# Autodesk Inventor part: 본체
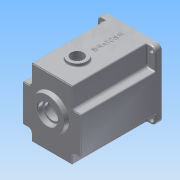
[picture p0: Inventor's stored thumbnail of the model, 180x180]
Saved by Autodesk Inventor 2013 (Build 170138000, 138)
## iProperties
Created: 2016-02
Part Number: 본체
Material: 알루미늄 6061
Document SubType Name: Modeling
Designer: mduedu
Density: 1 g/cm^3
Author: mduedu
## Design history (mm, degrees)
sketch "스케치1"
  geometry: L1 (-47, -47)-(47, -47); L2 (47, -47)-(47, 63); L3 (47, 63)-(-47, 63); L4 (-47, 63)-(-47, -47); 2 further points
  constraints: 8 end point, 2 parallel, 1 horizontal, 1 midpoint, 1 perpendicular, 1 vertical alignment
  dimensions: "d0" = 94 distance of L2.end L3.end; "d155" = 110 distance of L1.end L2.end; "d156" = 47 distance from line of L1 point (0, 0)
extrude "돌출1" new body sketch "스케치1" distance "d2" = 130; taper "d3" = 0 deg
sketch "스케치3"
  geometry: C1 r 40 at (0, 0); 1 further point
  constraints: 1 centre point, 1 coincident
  dimensions: "d9" = 80 diameter of C1
extrude "돌출3" cut sketch "스케치3" distance "d11" = 121; taper "d12" = 0 deg
sketch "스케치4"
  geometry: C1 r 21 at (0, 11); 1 further point
  constraints: 1 centre point, 1 vertical alignment
  dimensions: "d13" = 21 radius of C1; "d15" = 11 distance of point (0, 0) C1.centre
extrude "돌출4" join sketch "스케치4" distance "d16" = 7; taper "d17" = 0 deg
sketch "스케치5"
  geometry: C1 r 15 at (0, -20); 1 further point
  constraints: 1 centre point, 1 vertical alignment
  dimensions: "d18" = 15 radius of C1; "d20" = 20 distance of point (0, 0) C1.centre
extrude "돌출5" join sketch "스케치5" distance "d21" = 7; taper "d22" = 0 deg
sketch "스케치6"
  geometry: C1 r 28 at (0, 11); A1 r 21 centre (0, 11) between (8.978, -7.984) and (-8.978, -7.984) reference; 1 further point
  constraints: 1 centre point, 1 coincident
  dimensions: "d23" = 56 diameter of C1
extrude "돌출6" join sketch "스케치6" distance "d25" = 7; taper "d26" = -10 deg
hole "구멍1" diameter "d29" = 35; stored, may be unused: countersink angle "d33" = 90 deg, drill point angle "d35" = 0 deg; dims "d27" = 10, "d28" = 10, "d30" = 6, "d31" = 4, "d32" = 2, "d34" = 10
hole "구멍2" diameter "d38" = 22; stored, may be unused: countersink angle "d42" = 90 deg, drill point angle "d44" = 0 deg; dims "d36" = 10, "d37" = 10, "d39" = 6, "d40" = 4, "d41" = 2, "d43" = 7
hole "구멍3" diameter "d47" = 19; stored, may be unused: countersink angle "d51" = 90 deg, drill point angle "d53" = 0 deg; dims "d45" = 10, "d46" = 10, "d48" = 6, "d49" = 4, "d50" = 2, "d52" = 1
hole "구멍4" diameter "d56" = 32; stored, may be unused: countersink angle "d60" = 90 deg, drill point angle "d62" = 0 deg; dims "d54" = 10, "d55" = 10, "d57" = 6, "d58" = 4, "d59" = 2, "d61" = 8
hole "구멍5" diameter "d65" = 25; stored, may be unused: countersink angle "d69" = 90 deg, drill point angle "d71" = 0 deg; dims "d63" = 10, "d64" = 10, "d66" = 6, "d67" = 4, "d68" = 2, "d70" = 8
fillet "모깎기2" dims "d73" = 0.3
fillet "모깎기3" dims "d74" = 2
chamfer "모따기1" distance "d75" = 1; stored, may be unused: second distance "d76" = 2, angle "d77" = 45 deg
fillet "모깎기4" dims "d78" = 3
sketch "스케치16"
  geometry: L1 (-23, 32.726)-(23, 32.726); L2 (23, 32.726)-(23, 53); L3 (23, 53)-(-23, 53); L4 (-23, 53)-(-23, 32.726); L5 (-47, 63)-(47, 63) reference; 3 further points
  constraints: 8 end point, 2 parallel, 1 horizontal, 1 midpoint, 1 perpendicular, 1 vertical alignment, 2 other
  dimensions: "d160" = 46 distance of L2.end L3.end; "d163" = 10 distance between parallel lines of L3 L5
extrude "돌출15" cut sketch "스케치16" stored distance "d164" = 10; taper "d165" = 0 deg
fillet "모깎기5" dims "d79" = 2
fillet "모깎기15" dims "d166" = 5
sketch "스케치7"
  geometry: L1 (-23, 48)-(-23, 35.228) reference; L2 (23, 35.228)-(23, 48) reference; L3 (18, 53)-(-18, 53) reference; L4 (47, 63)-(47, -47) reference; L5 (47, -47)-(-47, -47) reference; L6 (-47, -47)-(-47, 63) reference; L7 (-47, 63)-(47, 63) reference; L8 (-26, 48)-(-26, 35.228); L9 (26, 35.228)-(26, 48); L10 (18, 56)-(-18, 56); C1 r 43 at (0, 0); A1 r 5 centre (-18, 48) between (-18, 53) and (-23, 48) reference; A2 r 5 centre (-28, 35.228) between (-24.889, 31.314) and (-23, 35.228) reference; A3 r 40 centre (0, 0) between (-24.889, 31.314) and (24.889, 31.314) reference; A4 r 5 centre (28, 35.228) between (23, 35.228) and (24.889, 31.314) reference; A5 r 5 centre (18, 48) between (23, 48) and (18, 53) reference; A6 r 8 centre (-18, 48) between (-18, 56) and (-26, 48); A7 r 2 centre (-28, 35.228) between (-26.756, 33.662) and (-26, 35.228); A8 r 43 centre (0, 0) between (-26.756, 33.662) and (26.756, 33.662); A9 r 2 centre (28, 35.228) between (26, 35.228) and (26.756, 33.662); A10 r 8 centre (18, 48) between (26, 48) and (18, 56); 1 further point
  constraints: 10 point on circle, 6 centre point, 6 end point, 1 coincident, 7 other
  dimensions: "d80" = 86 diameter of C1; "d167" = 3 distance between parallel lines of L3 L10
extrude "돌출7" cut sketch "스케치7" distance "d83" = 9; taper "d84" = 0 deg
sketch "스케치8" dims "d168" = 36
  geometry: L1 (-36, 4)-(-39.799, 4); L2 (-36, -4)-(-39.799, -4); A1 r 4 centre (-36, 0) between (-36, 4) and (-36, -4); A2 r 40 centre (0, 0) between (-24.889, 31.314) and (24.889, 31.314) reference; A3 r 40 centre (0, 0) between (-39.799, 4) and (-39.799, -4); 2 further points
  constraints: 5 point on circle, 4 end point, 2 centre point, 2 coincident, 2 horizontal alignment, 2 tangent, 1 horizontal, 1 parallel, 2 other
  dimensions: "d169" = 4 radius of A1
extrude "돌출9" join sketch "스케치8" stored distance "d89" = 9; taper "d90" = 0 deg
fillet "모깎기6" dims "d91" = 3.5
sketch "스케치9"
  geometry: L1 (47, 63)-(-47, 63) reference; L2 (47, -47)-(47, 63) reference; L3 (47, 63)-(33, 63); L4 (33, 63)-(33, 30); L5 (33, 30)-(47, 30); L6 (47, 30)-(47, 63); 2 further points
  constraints: 8 end point, 2 parallel, 1 horizontal, 1 perpendicular
  dimensions: "d95" = 33 distance from line of L4 point (0, 0); "d96" = 30 distance from line of L5 point (0, 0)
extrude "돌출10" cut sketch "스케치9" distance "d97" = 120; taper "d98" = 0 deg
sketch "스케치11"
  geometry: L1 (-40, -40)-(40, -40); L2 (40, -40)-(40, 56); L3 (40, 56)-(-40, 56); L4 (-40, 56)-(-40, -40); L5 (-47, -47)-(47, -47) reference; L6 (47, 63)-(-47, 63) reference; L7 (-47, 63)-(-47, -47) reference; C1 r 3.5 at (-40, 56); C2 r 3.5 at (40, 56); C3 r 3.5 at (40, -40); C4 r 3.5 at (-40, -40); 1 further point
  constraints: 8 end point, 4 centre point, 4 coincident, 3 equal radius, 2 parallel, 1 horizontal, 1 perpendicular
  dimensions: "d109" = 80 distance of L2.end L3.end; "d112" = 7 diameter of C1; "d157" = 7 distance from line of L1.start L5; "d158" = 7 distance between parallel lines of L6 L3; "d159" = 7 distance from line of L7 L3.end
extrude "돌출12" cut sketch "스케치11" stored distance "d113" = 63; taper "d114" = 0 deg
fillet "모깎기7" dims "d115" = 8
fillet "모깎기8" dims "d116" = 5
fillet "모깎기11" dims "d119" = 2
fillet "모깎기12" dims "d120" = 2
fillet "모깎기13" dims "d121" = 2
sketch "스케치12"
  geometry: 3 further points
  constraints: 2 horizontal alignment
hole "구멍6" sketch "스케치12" at (36, 0), (-36, 0) diameter "d122" = 3.242; stored, may be unused: countersink angle "d126" = 90 deg, drill point angle "d128" = 120 deg; dims "d123" = 7, "d124" = 4, "d125" = 2, "d127" = 9
sketch "스케치13"
  geometry: L1 (-33, 35)-(-33, 61) reference; L2 (-31, 63)-(31, 63) reference; L3 (33, 61)-(33, 35) reference; L4 (33, -35)-(33, -45) reference; L5 (31, -47)-(-31, -47) reference; L6 (-33, -45)-(-33, -35) reference; L7 (38, 30)-(45, 30) reference; L8 (47, 28)-(47, -28) reference; L9 (45, -30)-(38, -30) reference; L10 (-38, -30)-(-45, -30) reference; L11 (-47, -28)-(-47, 28) reference; L12 (-45, 30)-(-38, 30) reference; L13 (31, 62)-(-31, 62); L14 (-32, 61)-(-32, 35); L15 (-38, 29)-(-45, 29); L16 (-46, 28)-(-46, -28); L17 (-45, -29)-(-38, -29); L18 (-32, -35)-(-32, -45); L19 (-31, -46)-(31, -46); L20 (32, -45)-(32, -35); L21 (38, -29)-(45, -29); L22 (46, -28)-(46, 28); L23 (45, 29)-(38, 29); L24 (32, 35)-(32, 61); L25 (38, 30)-(45, 30) reference; L26 (47, 28)-(47, -28) reference; L27 (45, -30)-(38, -30) reference; L28 (33, -35)-(33, -45) reference; L29 (31, -47)-(-31, -47) reference; L30 (-33, -45)-(-33, -35) reference; L31 (-38, -30)-(-45, -30) reference; L32 (-47, -28)-(-47, 28) reference; L33 (-45, 30)-(-38, 30) reference; L34 (-33, 35)-(-33, 61) reference; L35 (33, 61)-(33, 35) reference; L36 (-31, 63)-(31, 63) reference; C1 r 16 at (0, 11) reference; C2 r 28 at (0, 11) reference; C3 r 16 at (0, 11) reference; C4 r 28 at (0, 11) reference; A1 r 5 centre (-38, 35) between (-38, 30) and (-33, 35) reference; A2 r 2 centre (-31, 61) between (-31, 63) and (-33, 61) reference; A3 r 2 centre (31, 61) between (33, 61) and (31, 63) reference; A4 r 5 centre (38, 35) between (33, 35) and (38, 30) reference; A5 r 5 centre (38, -35) between (38, -30) and (33, -35) reference; A6 r 2 centre (31, -45) between (31, -47) and (33, -45) reference; A7 r 2 centre (-31, -45) between (-33, -45) and (-31, -47) reference; A8 r 5 centre (-38, -35) between (-33, -35) and (-38, -30) reference; A9 r 2 centre (45, 28) between (47, 28) and (45, 30) reference; A10 r 2 centre (45, -28) between (45, -30) and (47, -28) reference; A11 r 2 centre (-45, -28) between (-47, -28) and (-45, -30) reference; A12 r 2 centre (-45, 28) between (-45, 30) and (-47, 28) reference; A13 r 1 centre (-31, 61) between (-31, 62) and (-32, 61); A14 r 6 centre (-38, 35) between (-38, 29) and (-32, 35); A15 r 1 centre (-45, 28) between (-45, 29) and (-46, 28); A16 r 1 centre (-45, -28) between (-46, -28) and (-45, -29); A17 r 6 centre (-38, -35) between (-32, -35) and (-38, -29); A18 r 1 centre (-31, -45) between (-32, -45) and (-31, -46); A19 r 1 centre (31, -45) between (31, -46) and (32, -45); A20 r 6 centre (38, -35) between (38, -29) and (32, -35); A21 r 1 centre (45, -28) between (45, -29) and (46, -28); A22 r 1 centre (45, 28) between (46, 28) and (45, 29); A23 r 6 centre (38, 35) between (32, 35) and (38, 29); A24 r 1 centre (31, 61) between (32, 61) and (31, 62); A25 r 5 centre (38, 35) between (33, 35) and (38, 30) reference; A26 r 2 centre (45, 28) between (47, 28) and (45, 30) reference; A27 r 2 centre (45, -28) between (45, -30) and (47, -28) reference; A28 r 5 centre (38, -35) between (38, -30) and (33, -35) reference; A29 r 2 centre (31, -45) between (31, -47) and (33, -45) reference; A30 r 2 centre (-31, -45) between (-33, -45) and (-31, -47) reference; A31 r 5 centre (-38, -35) between (-33, -35) and (-38, -30) reference; A32 r 2 centre (-45, -28) between (-47, -28) and (-45, -30) reference; A33 r 2 centre (-45, 28) between (-45, 30) and (-47, 28) reference; A34 r 5 centre (-38, 35) between (-38, 30) and (-33, 35) reference; A35 r 2 centre (-31, 61) between (-31, 63) and (-33, 61) reference; A36 r 2 centre (31, 61) between (33, 61) and (31, 63) reference
  constraints: 24 end point, 24 point on circle, 12 centre point, 23 other
  dimensions: "d154" = 1 distance between parallel lines of L13 L2
extrude "돌출13" cut sketch "스케치13" distance "d130" = 1; taper "d131" = 0 deg
fillet "모깎기14" dims "d147" = 0.3
sketch "스케치15"
  geometry: L1 (78, 0)-(0, 0) reference; 3 further points
  constraints: 1 midpoint, 1 vertical alignment, 1 other
  dimensions: "d148" = 40 distance of point (39, -40) point (39, 0)
feature "엠보싱1" sketch "스케치15" dims "d22" = 0, "d149" = 0.5, "d150" = 0
chamfer "모따기4" distance "d151" = 1; stored, may be unused: second distance "d152" = 2, angle "d153" = 45 deg
sketch "스케치17"
  geometry: L1 (39.004, -17.213)-(39.004, -18.809) reference; L2 (39.004, -18.809)-(38.548, -18.809) reference; L3 (38.548, -18.809)-(38.548, -17.213) reference; L4 (38.548, -17.213)-(35.455, -17.213) reference; L5 (35.455, -17.213)-(35.455, -16.822) reference; L6 (35.772, -16.659)-(42.578, -16.659) reference; L7 (42.578, -16.659)-(42.578, -17.213) reference; L8 (42.578, -17.213)-(39.004, -17.213) reference; L9 (38.223, -56.73)-(38.695, -56.73) reference; L10 (38.695, -56.73)-(38.695, -58.073) reference; L11 (38.695, -58.073)-(40.787, -58.073) reference; L12 (40.787, -58.073)-(40.787, -58.643) reference; L13 (40.787, -58.643)-(35.398, -58.643) reference; L14 (35.398, -58.643)-(35.398, -58.277) reference; L15 (35.715, -58.073)-(38.223, -58.073) reference; L16 (38.223, -58.073)-(38.223, -56.73) reference; L17 (41.927, -57.813)-(42.383, -57.813) reference; L18 (42.383, -57.813)-(42.383, -63.031) reference; L19 (42.383, -63.031)-(40.429, -63.031) reference; L20 (40.429, -63.031)-(40.429, -62.608) reference; L21 (40.689, -62.478)-(41.927, -62.478) reference; L22 (41.927, -62.478)-(41.927, -57.813) reference; L23 (36.09, -60.849)-(36.09, -62.624) reference; L24 (36.09, -62.624)-(35.666, -62.624) reference; L25 (35.666, -62.624)-(35.666, -60.849) reference; L26 (35.666, -60.849)-(36.09, -60.849) reference; L27 (37.058, -64.057)-(36.635, -64.057) reference; L28 (36.635, -64.057)-(36.635, -59.539) reference; L29 (36.635, -59.539)-(37.058, -59.539) reference; L30 (37.058, -59.539)-(37.058, -64.057) reference; L31 (42.138, -43.501)-(40.307, -44.168) reference; L32 (40.307, -44.168)-(40.307, -46.871) reference; L33 (40.307, -46.871)-(42.138, -47.555) reference; L34 (42.138, -47.555)-(42.138, -48.133) reference; L35 (42.138, -48.133)-(36.138, -45.853) reference; L36 (36.138, -45.853)-(36.138, -45.202) reference; L37 (36.138, -45.202)-(42.138, -42.923) reference; L38 (42.138, -42.923)-(42.138, -43.501) reference; L39 (36.725, -45.536)-(39.81, -46.684) reference; L40 (39.81, -46.684)-(39.81, -44.364) reference; L41 (39.81, -44.364)-(36.725, -45.536) reference; L42 (40.022, -52.114)-(40.022, -49.94) reference; L43 (40.022, -49.94)-(42.57, -49.94) reference; L44 (42.57, -49.94)-(42.57, -50.494) reference; L45 (42.57, -50.494)-(40.469, -50.494) reference; L46 (40.469, -50.494)-(40.469, -55.094) reference; L47 (40.469, -55.094)-(40.022, -55.094) reference; L48 (40.022, -55.094)-(40.022, -52.659) reference; L49 (40.022, -52.659)-(38.556, -52.659) reference; L50 (38.556, -52.659)-(38.556, -55.973) reference; L51 (38.556, -55.973)-(38.109, -55.973) reference; L52 (38.109, -55.973)-(38.109, -50.73) reference; L53 (36.106, -50.388)-(36.106, -54.955) reference; L54 (36.106, -54.955)-(35.65, -54.955) reference; L55 (35.65, -54.955)-(35.65, -49.81) reference; L56 (38.109, -50.136)-(38.109, -48.768) reference; L57 (38.109, -48.768)-(38.556, -48.768) reference; L58 (38.556, -48.768)-(38.556, -52.114) reference; L59 (38.556, -52.114)-(40.022, -52.114) reference; L60 (36.138, -38.168)-(36.635, -38.168) reference; L61 (36.635, -38.168)-(36.635, -40.041) reference; L62 (36.635, -40.041)-(42.138, -40.041) reference; L63 (42.138, -40.041)-(42.138, -40.586) reference; L64 (42.138, -40.586)-(36.635, -40.586) reference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; C1 r 10 at (39, -89); A1 r 4 centre (4, -12) between (8, -12) and (4, -8) reference; A2 r 4 centre (74, -12) between (74, -8) and (70, -12) reference; 61 further points
  constraints: 2 end point, 1 centre point, 1 midpoint, 1 point on line, 76 other
  dimensions: "d170" = 20 diameter of C1; "d171" = 41 distance from line of C1.centre L110
extrude "돌출16" cut sketch "스케치17" stored distance "d172" = 10; taper "d173" = 0 deg
sketch "스케치18"
  geometry: C1 r 10 at (39, -89) reference; C2 r 15 at (39, -89); 1 further point
  constraints: 1 centre point, 1 coincident
  dimensions: "d174" = 30 diameter of C2
extrude "돌출17" join sketch "스케치18" distance "d175" = 5; taper "d176" = 0 deg
fillet "모깎기16" dims "d177" = 2
sketch "스케치19"
  geometry: C1 r 10 at (18, 80) reference; C2 r 15 at (18, 80); 1 further point
  constraints: 1 centre point, 1 coincident
  dimensions: "d178" = 30 diameter of C2
extrude "돌출18" cut sketch "스케치19" distance "d181" = 5; taper "d182" = 0 deg
chamfer "모따기5" distance "d183" = 0.5; stored, may be unused: second distance "d184" = 2, angle "d185" = 45 deg
node "솔리드1"
pattern_circular "원형 패턴1" dims angle "d93" = 360 deg
mirror "대칭1"
mirror "대칭2"
node "절단 모서리 투영1"
node "절단 모서리 투영2"
node "절단 모서리 투영3"
node "절단 모서리 투영4"
